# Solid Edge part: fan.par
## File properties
Author: Julian Frimmel
Template: Iso Metric Part.par
Last saved by: Julian Frimmel
Revision: 6
Application: Solid Edge
Genauigkeit: 0,990
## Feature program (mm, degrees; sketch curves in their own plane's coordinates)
helix protrusion "Schraubenflächenausprägung_2"  NumberOfTurns = 0.08
pattern "unnamed Pattern 1" of "Schraubenflächenausprägung_2"
pattern "unnamed Pattern 2"
Other named dimensions: "Muster_2": XCount = 7; XOffset = 51.4286 deg
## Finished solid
Body 1: solid body, 54 faces, 136 edges, 84 vertices.
  Faces by surface: cylinder 23, plane 17, spline 14
  Edges by curve: line 42, intersection 28, spline 28, circle 24, curve on surface 14
Bounding box of the edges (mm; curved faces can reach further): 89.887 x 88.662 x 23.809, from (-44.8982, -44.9984, 0) to (44.9886, 43.6632, 23.8087).
Cylindrical faces by radius (mm): R1 x7, R1.5 x1, R5 x7, R15 x1, R45 x7
Planar faces by outward normal: +z 1, -y 1, -z 2, oblique 13
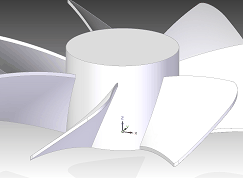
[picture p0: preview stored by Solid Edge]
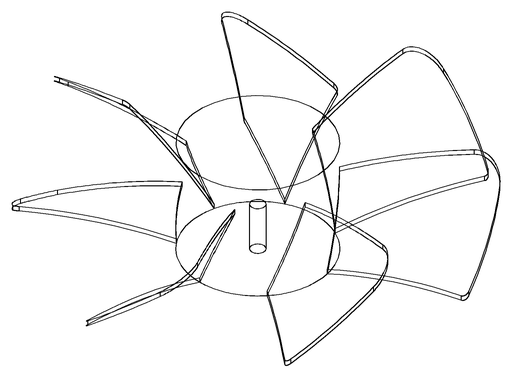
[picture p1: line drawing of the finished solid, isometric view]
